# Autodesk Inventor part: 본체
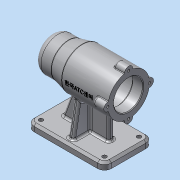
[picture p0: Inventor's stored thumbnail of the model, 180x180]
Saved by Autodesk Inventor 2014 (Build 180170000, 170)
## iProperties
Created: 2019-07
Part Number: 본체
Material: 알루미늄 6061
Document SubType Name: Modeling
Designer: kb542-23
Density: 2.71 g/cm^3
Appearance: 알루미늄 - 평지
Mass: 646.775 g
Surface Area: 654.094 cm^2
Volume: 238.662 cm^3
Author: kb542-23
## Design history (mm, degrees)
sketch "스케치1"
  geometry: L1 (-56, 0)-(56, 0); L2 (-56, 0)-(-56, 25); L3 (-56, 25)-(-31, 25); L4 (-31, 25)-(-11, 30); L5 (-11, 30)-(56, 30); L6 (56, 30)-(56, 0); L7 (56, 21)-(41, 21); L8 (41, 21)-(41, 24); L9 (41, 24)-(-13, 24); L10 (-13, 24)-(-13, 21); L11 (-13, 21)-(-25, 21); L12 (-25, 21)-(-25, 17.5); L13 (-25, 17.5)-(-43, 17.5); L14 (-43, 17.5)-(-43, 16); L15 (-43, 16)-(-47, 16); L16 (-47, 16)-(-47, 10.5); L17 (-47, 10.5)-(-50, 10.5); L18 (-50, 10.5)-(-50, 0); L19 (-25, -21)-(-25, -17.5); L20 (-25, -17.5)-(-43, -17.5); L21 (-43, -17.5)-(-43, -16); L22 (-43, -16)-(-47, -16); L23 (-47, -16)-(-47, -10.5); L24 (-47, -10.5)-(-50, -10.5); L25 (-56, -25)-(-31, -25); L26 (-50, -10.5)-(-50, 0); L27 (-56, 0)-(-56, -25); L28 (-13, -24)-(-13, -21); L29 (-13, -21)-(-25, -21); L30 (-31, -25)-(-11, -30); L31 (41, -21)-(41, -24); L32 (56, -30)-(56, 0); L33 (56, -21)-(41, -21); L34 (-11, -30)-(56, -30); L35 (41, -24)-(-13, -24); 2 further points
  constraints: 70 end point, 16 symmetric about line, 9 perpendicular, 7 parallel, 3 point on line, 2 midpoint, 1 coincident, 1 horizontal
  dimensions: "d0" = 112 distance between parallel lines of L6 L2; "d1" = 60 diameter of L5 L1; "d3" = 50 diameter of L3 L1; "d4" = 48 diameter of L9 L1; "d5" = 42 diameter of L7 L1; "d6" = 15 distance between parallel lines of L8 L6; "d7" = 54 distance between parallel lines of L10 L8; "d9" = 42 diameter of L11 L1; "d10" = 35 diameter of L13 L1; "d11" = 32 diameter of L15 L1; "d12" = 21 diameter of L17 L1; "d13" = 3 distance between parallel lines of L16 L18; "d14" = 4 distance between parallel lines of L14 L16; "d15" = 18 distance between parallel lines of L12 L14; "d16" = 12 distance between parallel lines of L10 L12; "d96" = 25 distance from line of L25.end L27; "d97" = 45 horizontal distance of L30.end L25.start
revolve "회전1" sketch "스케치1" stored, may be unused: angle "d22" = 90 deg
sketch "스케치2"
  geometry: A1 r 30 centre (0, 0) between (0, 30) and (-5.97, 29.4) reference; A2 r 6 centre (0, 30) between (5.97, 29.4) and (-5.97, 29.4)
  constraints: 5 point on circle, 1 centre point, 1 coincident, 1 vertical alignment
  dimensions: "d23" = 6 radius of A2
extrude "돌출1" join sketch "스케치2" distance "d24" = 16; taper "d25" = 0 deg
sketch "스케치3"
  geometry: A1 r 6 centre (-30, -30) between (-29.4, -24.03) and (-29.4, -35.97) reference; A2 r 6 centre (0, -60) between (-5.97, -59.4) and (5.97, -59.4) reference; A3 r 6 centre (30, -30) between (29.4, -35.97) and (29.4, -24.03) reference; A4 r 6 centre (0, 0) between (5.97, -0.6) and (-5.97, -0.6) reference; 4 further points
  constraints: 4 coincident
hole "구멍1" sketch "스케치3" at (0, 0), (-30, -30), (30, -30), (0, -60) diameter "d29" = 3.242; stored, may be unused: countersink angle "d33" = 90 deg, drill point angle "d35" = 118 deg; dims "d30" = 8, "d31" = 4, "d32" = 2, "d34" = 11
node "작업 평면1"
sketch "스케치4"
  geometry: L1 (-25, -56)-(25, -56); L2 (35, -46)-(35, 46); L3 (25, 56)-(-25, 56); L4 (-35, 46)-(-35, -46); L5 (-35, -56)-(35, 56); L6 (35, -56)-(-35, 56); A1 r 10 centre (-25, -46) between (-35, -46) and (-25, -56); A2 r 10 centre (25, -46) between (25, -56) and (35, -46); A3 r 10 centre (25, 46) between (35, 46) and (25, 56); A4 r 10 centre (-25, 46) between (-25, 56) and (-35, 46); 1 further point
  constraints: 12 end point, 8 point on circle, 8 point on line, 8 tangent, 4 centre point, 3 equal radius, 2 midpoint, 2 parallel, 1 horizontal, 1 perpendicular
  dimensions: "d37" = 112 distance of L6.end L5.start; "d38" = 70 distance of L5.end L6.end; "d39" = 35 distance from line of point (0, 0) L4 (derived); "d40" = 56 distance from line of point (0, 0) L3 (derived); "d41" = 10 radius of A1
extrude "돌출2" join sketch "스케치4" distance "d42" = 10; taper "d43" = 0 deg
sketch "스케치5"
  geometry: L1 (-35, 70)-(-25, 70) reference; L2 (-28, 70)-(-19.654, 22.666); L3 (-35, 80)-(-35, 70) reference; L4 (28, 70)-(19.654, 22.666); L5 (25, 70)-(35, 70) reference; L6 (-28, 70)-(28, 70); L7 (35, 80)-(35, 70) reference; A1 r 30 centre (0, 0) between (-5.97, 29.4) and (-29.4, 5.97) reference; A2 r 30 centre (0, 0) between (29.4, 5.97) and (5.97, 29.4) reference; A3 r 30 centre (0, 0) between (5.97, 29.4) and (-5.97, 29.4) reference; A4 r 30 centre (0, 0) between (19.654, 22.666) and (-19.654, 22.666); 1 further point
  constraints: 6 end point, 3 point on circle, 1 centre point, 1 coincident, 1 point on line
  dimensions: "d44" = 7 distance from line of L2.start L3; "d45" = 100 deg angle of L1 L2; "d99" = 7 distance of L5.end L4.start; "d102" = 100 deg angle of L5 L4; "d104" = 90 deg angle of L7 L6
extrude "돌출3" join sketch "스케치5" stored distance "d46" = 8; taper "d47" = 0 deg
sketch "스케치7"
  geometry: L1 (46, 70)-(-46, 70) reference; L2 (-36, 70)-(-20.57, 27.607); L3 (-56, 80)-(-56, 70) reference; L4 (-31, 25)-(-11, 30) reference; L5 (31, 70)-(31, 30); L6 (56, 80)-(56, 70) reference; L7 (-11, 30)-(40, 30) reference; 1 further point
  constraints: 4 end point, 4 point on line, 1 parallel
  dimensions: "d51" = 20 distance from line of L3 L2.start; "d52" = 110 deg angle of L1 L2; "d53" = 25 distance between parallel lines of L5 L6
feature "리브1" dims "d54" = 1, "d55" = 8, "d56" = 0, "d57" = 0, "d58" = 1, "d59" = 1
feature "리브2" dims "d60" = 1, "d61" = 8, "d62" = 0, "d63" = 0, "d64" = 1, "d65" = 1
sketch "스케치8"
  geometry: A1 r 10 centre (25, -46) between (25, -56) and (35, -46) reference; A2 r 10 centre (25, 46) between (35, 46) and (25, 56) reference; A3 r 10 centre (-25, 46) between (-25, 56) and (-35, 46) reference; A4 r 10 centre (-25, -46) between (-35, -46) and (-25, -56) reference; 5 further points
  constraints: 4 coincident
hole "구멍2" sketch "스케치8" at (25, -46), (25, 46), (-25, 46), (-25, -46) diameter "d66" = 6; stored, may be unused: countersink angle "d70" = 90 deg, drill point angle "d72" = 0 deg; dims "d67" = 8, "d68" = 4, "d69" = 2, "d71" = 11
chamfer "모따기1" distance "d73" = 3; stored, may be unused: second distance "d74" = 2, angle "d75" = 45 deg
fillet "모깎기1" dims "d76" = 10, "d78" = 3
fillet "모깎기2" dims "d77" = 0.3
chamfer "모따기2" distance "d79" = 1; stored, may be unused: second distance "d80" = 2, angle "d81" = 45 deg
fillet "모깎기3" dims "d82" = 3
fillet "모깎기4" dims "d83" = 3
fillet "모깎기5" dims "d84" = 1
node "작업 평면6"
sketch "스케치12"
  geometry: L1 (-56, -30.171)-(-56, -36) reference; 2 further points
  constraints: 1 horizontal alignment, 1 other
  dimensions: "d91" = 42 distance from line of L1 point (-14, 0)
feature "엠보싱1" sketch "스케치12" dims "d0" = 112, "d1" = 60, "d3" = 50, "d4" = 48, "d5" = 42, "d6" = 15, "d7" = 54, "d9" = 42, "d10" = 35, "d11" = 32, "d12" = 21, "d13" = 3, "d14" = 4, "d15" = 18, "d16" = 12, "d92" = 0.5, "d93" = 0, "d96" = 25, "d97" = 45
node "솔리드1"
pattern_circular "원형 패턴1" dims angle "d27" = 360 deg
other parameters: "d90" = 0
